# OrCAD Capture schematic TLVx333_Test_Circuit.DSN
size A; title: TLVx333 2-µV VOS, 0.02-µV/°C, 17-µA, CMOS Operational; rev: 1.3; note: Datasheet: SBOS751  EVM: N/A
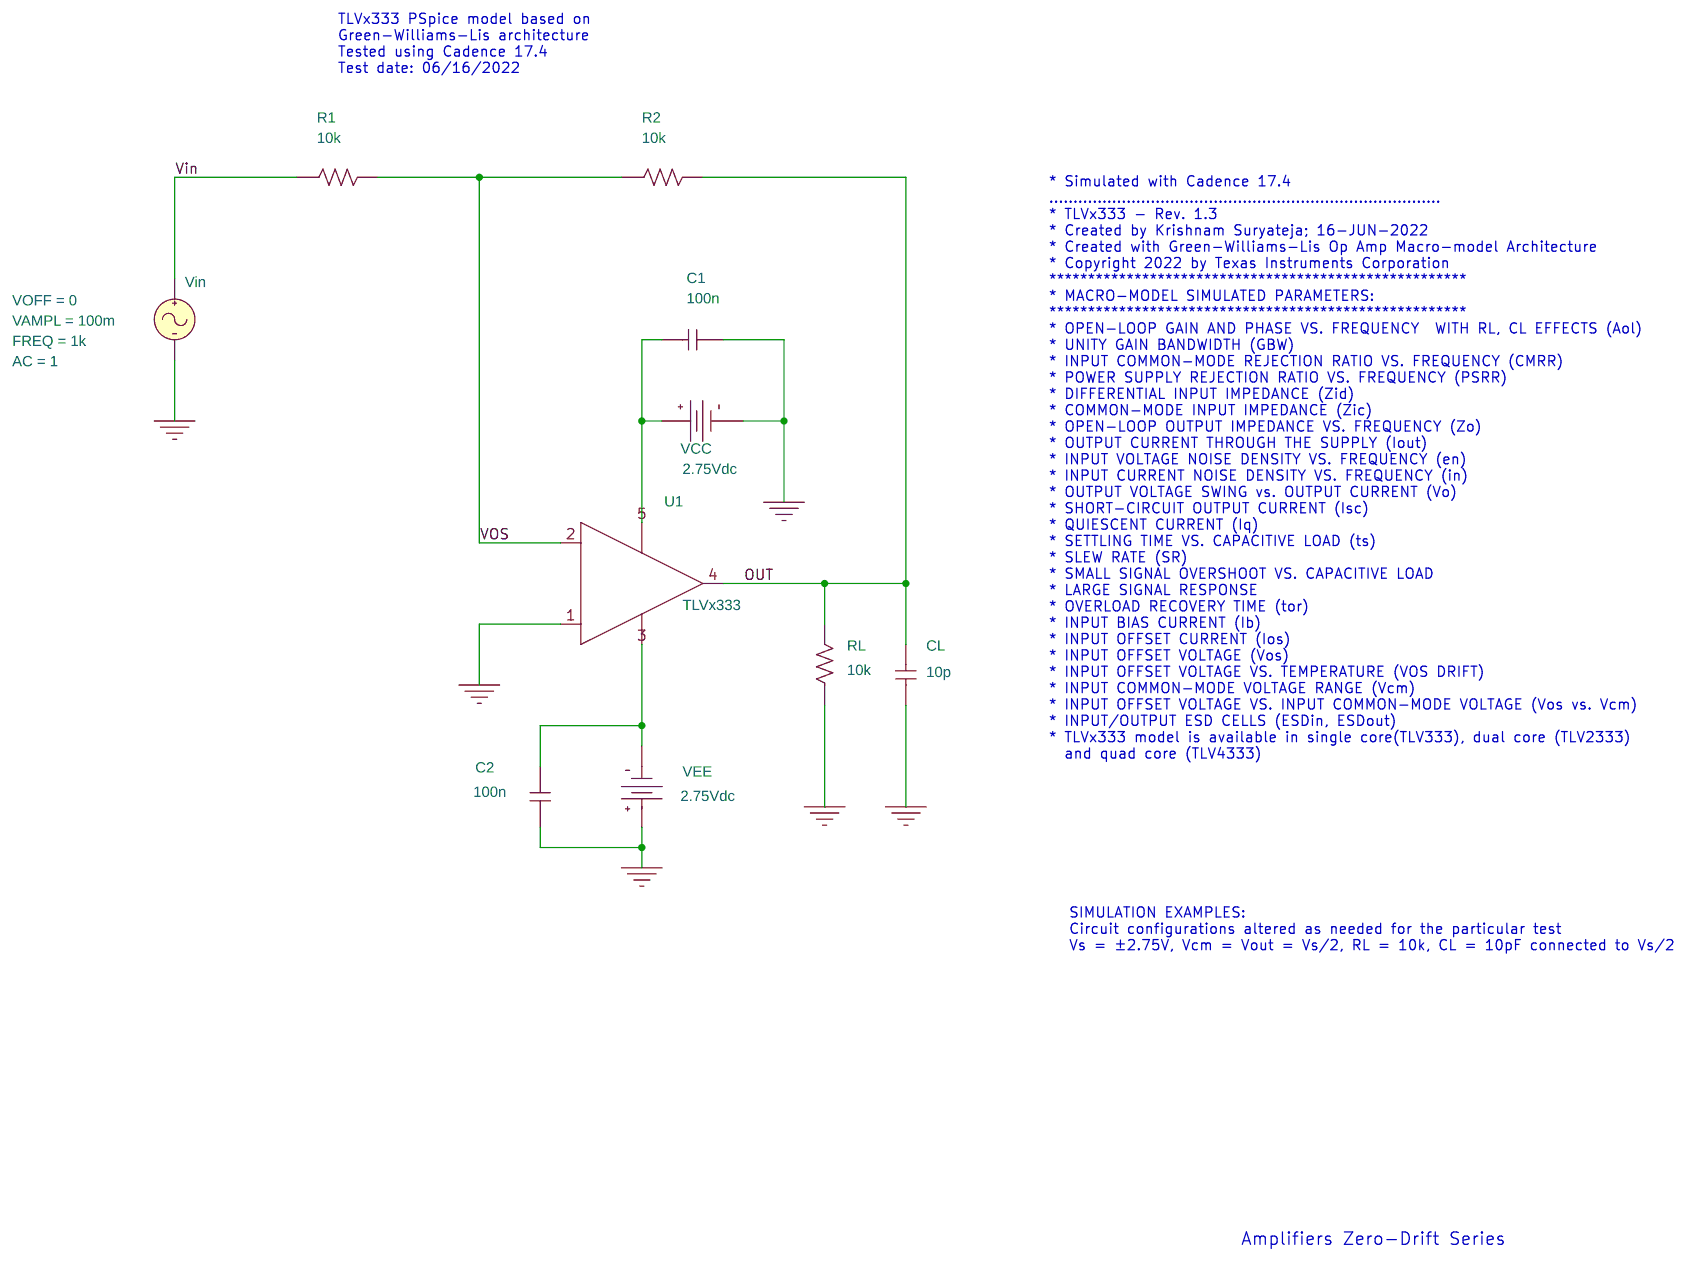
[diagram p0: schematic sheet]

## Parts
C1  100n  [cap196]
C2  100n  [cap196]
CL  10p  [cap196]
R1  10k  [AXRC05]
R2  10k  [AXRC05]
RL  10k  [AXRC05]
U1  TLVx333
VCC  VDC
VEE  VDC
Vin  VSIN

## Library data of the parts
C1 C2 CL = C
R1 R2 RL = R
U1 = TLVx333
VCC VEE = VDC: DC: 2.75Vdc
Vin = VSIN: AC: 1; FREQ: 1k; VAMPL: 100m; VOFF: 0

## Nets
Vin: R1.1 Vin.1(+)
0: C1.2 C2.1 CL.2 RL.1 U1.1(+) VCC.1(-) VEE.0(+) Vin.2(-)
OUT: CL.1 R2.2 RL.2 U1.4(OUT)
VOS: R1.2 R2.1 U1.2(-)
N27303: C1.1 U1.5(V+) VCC.0(+)
N27354: C2.2 U1.3(V-) VEE.1(-)

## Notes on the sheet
- TLVx333 PSpice model based on
  Green-Williams-Lis architecture
  Tested using Cadence 17.4
  Test date: 06/16/2022
- * Simulated with Cadence 17.4
  .................................................................................
  * TLVx333 - Rev. 1.3
  * Created by Krishnam Suryateja; 16-JUN-2022
  * Created with Green-Williams-Lis Op Amp Macro-model Architecture
  * Copyright 2022 by Texas Instruments Corporation
  ******************************************************
  * MACRO-MODEL SIMULATED PARAMETERS:
  ******************************************************
  * OPEN-LOOP GAIN AND PHASE VS. FREQUENCY  WITH RL, CL EFFECTS (Aol)
  * UNITY GAIN BANDWIDTH (GBW)
  * INPUT COMMON-MODE REJECTION RATIO VS. FREQUENCY (CMRR)
  * POWER SUPPLY REJECTION RATIO VS. FREQUENCY (PSRR)
  * DIFFERENTIAL INPUT IMPEDANCE (Zid)
  * COMMON-MODE INPUT IMPEDANCE (Zic)
  * OPEN-LOOP OUTPUT IMPEDANCE VS. FREQUENCY (Zo)
  * OUTPUT CURRENT THROUGH THE SUPPLY (Iout)
  * INPUT VOLTAGE NOISE DENSITY VS. FREQUENCY (en)
  * INPUT CURRENT NOISE DENSITY VS. FREQUENCY (in)
  * OUTPUT VOLTAGE SWING vs. OUTPUT CURRENT (Vo)
  * SHORT-CIRCUIT OUTPUT CURRENT (Isc)
  * QUIESCENT CURRENT (Iq)
  * SETTLING TIME VS. CAPACITIVE LOAD (ts)
  * SLEW RATE (SR)
  * SMALL SIGNAL OVERSHOOT VS. CAPACITIVE LOAD
  * LARGE SIGNAL RESPONSE
  * OVERLOAD RECOVERY TIME (tor)
  * INPUT BIAS CURRENT (Ib)
  * INPUT OFFSET CURRENT (Ios)
  * INPUT OFFSET VOLTAGE (Vos)
  * INPUT OFFSET VOLTAGE VS. TEMPERATURE (VOS DRIFT)
  * INPUT COMMON-MODE VOLTAGE RANGE (Vcm)
  * INPUT OFFSET VOLTAGE VS. INPUT COMMON-MODE VOLTAGE (Vos vs. Vcm)
  * INPUT/OUTPUT ESD CELLS (ESDin, ESDout)
  * TLVx333 model is available in single core(TLV333), dual core (TLV2333)
    and quad core (TLV4333)
- SIMULATION EXAMPLES:
  Circuit configurations altered as needed for the particular test
  Vs = ±2.75V, Vcm = Vout = Vs/2, RL = 10k, CL = 10pF connected to Vs/2
- Amplifiers Zero-Drift Series
